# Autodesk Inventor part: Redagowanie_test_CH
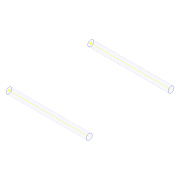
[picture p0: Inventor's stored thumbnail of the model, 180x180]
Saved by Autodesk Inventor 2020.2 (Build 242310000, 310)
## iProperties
Created: 2015-11
Part Number: Redagowanie_test_CH
Material: Ogólne
Document SubType Name: Modeling
Designer: F.Stasiak
Density: 1 g/cm^3
Appearance: Przezroczysty - niebieski
Catalog Web Link: www.expertbooks.pl
Manager: www.cadconsulting.pl
Company: Fabian Stasiak CAD Consulting
Author: F.Stasiak
Subject: Zbiór ćwiczeń. Autodesk Inventor 2020. Kurs Professional
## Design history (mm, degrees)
node "Płaszczyzna konstrukcyjna1"
node "Segment chłodzenia1"
  sketch "Szkic1"
    geometry: L1 (0, 0)-(0, -4); L2 (0, -4)-(108, -4); L3 (108, -4)-(108, 0); L4 (0, 0)-(108, 0)
    constraints: 8 end point, 2 perpendicular, 1 parallel
    dimensions: "d0" = 4 distance between parallel lines of L2 L4
  node "Punkt konstrukcyjny1"
  node "Oś konstrukcyjna1"
node "Płaszczyzna konstrukcyjna2"
node "Segment chłodzenia2"
  sketch "Szkic2"
    geometry: L1 (0, 0)-(0, -4); L2 (0, -4)-(108, -4); L3 (108, -4)-(108, 0); L4 (0, 0)-(108, 0)
    constraints: 8 end point, 2 perpendicular, 1 parallel
    dimensions: "d3" = 4 distance between parallel lines of L2 L4
  node "Punkt konstrukcyjny2"
  node "Oś konstrukcyjna2"
node "Bryła1"
revolve "Obrót1" stored, may be unused: angle "d1" = 0 deg
body "Srf1"
revolve "Obrót2" stored, may be unused: angle "d4" = 0 deg
body "Srf2"
feature "PowObrotowa1" dims angle "d2" = 0 deg
feature "PowObrotowa2" dims angle "d5" = 0 deg
